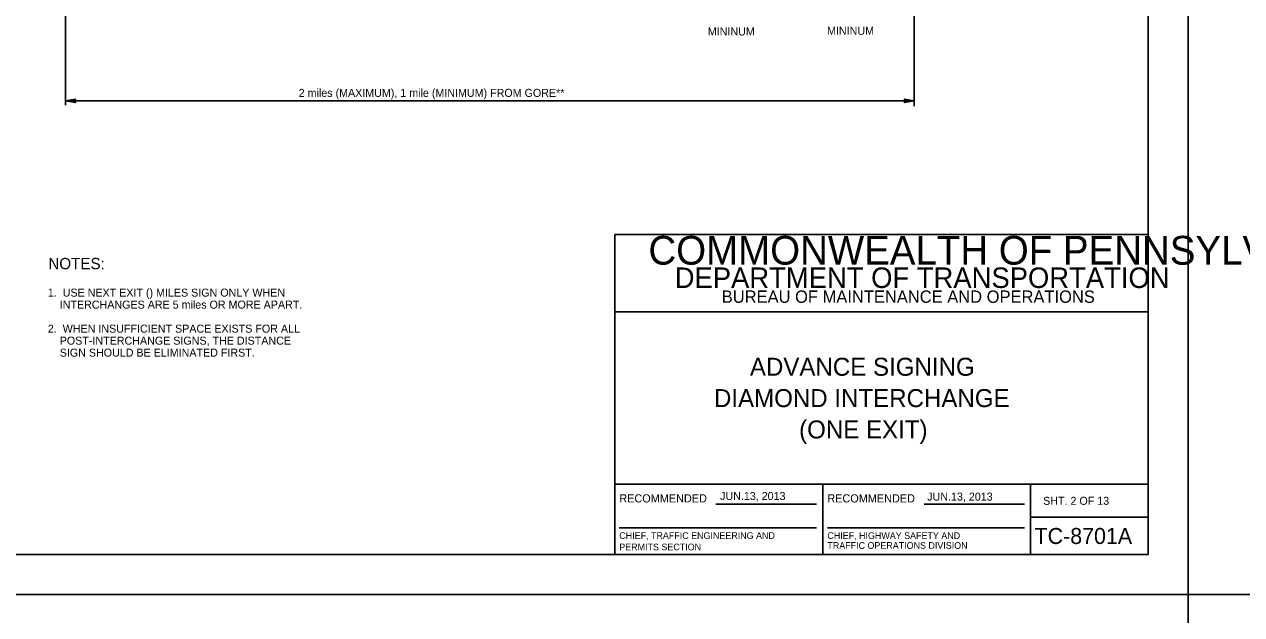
# Model space of a CAD drawing. Extents: x 644898 to 648326, y 298294 to 300670.
# Drawn here: x 646144 to 646600.3, y 300069 to 300290.3 of the extents above; entities that cross this region are included whole.
import ezdxf

# ---------------------------------------------------------------- set-up
doc = ezdxf.new("R2010")
doc.units = 0
for name, color, linetype in [('1', 7, 'Continuous'), ('2', 7, 'Continuous'), ('XCS-GRID-MIN', 7, 'Continuous')]:
    doc.layers.add(name, color=color, linetype=linetype)

msp = doc.modelspace()

# ---------------------------------------------------------------- linework, layer by layer
at = {"layer": '1'}
for p, q in [((646565.32, 300091.49), (646565.32, 300655.49)), ((646365.32, 300091.49), (646365.32, 300211.49)), ((646365.32, 300211.49), (646565.32, 300211.49)), ((646565.32, 300182.49), (646365.32, 300182.49)), ((646365.32, 300117.87), (646565.32, 300117.87)), ((646443.32, 300117.87), (646443.32, 300091.49)), ((646521.2, 300091.49), (646521.2, 300117.87)), ((646403.26, 300110.44), (646440.88, 300110.44)), ((646481.26, 300110.44), (646518.88, 300110.44)), ((646521.2, 300105.49), (646565.32, 300105.49)), ((646367.01, 300101.54), (646440.88, 300101.54)), ((646445.01, 300101.54), (646518.88, 300101.54)), ((646565.32, 300091.49), (645779.32, 300091.49)), ((645779.32, 300091.49), (646365.32, 300091.49))]:
    msp.add_line(p, q, dxfattribs=at)
at = {"layer": '2'}
for p, q in [((646477.57, 300377.74), (646477.57, 300259.62)), ((646159.45, 300363.62), (646159.45, 300259.99)), ((646477.57, 300261.62), (646159.45, 300261.62))]:
    msp.add_line(p, q, dxfattribs=at)
for points in [[(646162.95, 300261.12), (646162.82, 300261.37), (646159.45, 300261.62), (646162.95, 300261.12), (646163.2, 300260.99), (646159.45, 300261.62), (646162.82, 300261.74), (646162.95, 300261.99), (646159.45, 300261.62), (646163.2, 300262.24), (646162.95, 300261.99)], [(646474.07, 300262.12), (646474.2, 300261.87), (646477.57, 300261.62), (646474.07, 300262.12), (646473.82, 300262.24), (646477.57, 300261.62), (646474.2, 300261.49), (646474.07, 300261.24), (646477.57, 300261.62), (646473.82, 300260.99), (646474.07, 300261.24)]]:
    msp.add_lwpolyline(points, dxfattribs=at)
at = {"layer": 'XCS-GRID-MIN'}
for points in [[(645739.32, 300670.49), (646580.32, 300670.49), (646580.32, 300076.49), (645739.32, 300076.49)], [(646580.32, 300670.49), (647421.32, 300670.49), (647421.32, 300076.49), (646580.32, 300076.49)], [(645739.32, 300076.49), (646580.32, 300076.49), (646580.32, 299482.49), (645739.32, 299482.49)], [(646580.32, 300076.49), (647421.32, 300076.49), (647421.32, 299482.49), (646580.32, 299482.49)]]:
    msp.add_lwpolyline(points, close=True, dxfattribs=at)

# ---------------------------------------------------------------- texts
at = {"layer": '1'}
for s, height, p in [('COMMONWEALTH OF PENNSYLVANIA', 10.7828, (646377.92, 300200.22)), ('DEPARTMENT OF TRANSPORTATION', 7.6837, (646387.78, 300191.48)), ('BUREAU OF MAINTENANCE AND OPERATIONS', 4.6253, (646405.42, 300185.91)), ('ADVANCE SIGNING', 6.75, (646415.97, 300158.56)), ('DIAMOND INTERCHANGE', 6.75, (646402.5, 300146.81)), ('(ONE EXIT)', 6.75, (646434.42, 300135.06)), ('RECOMMENDED', 3.048, (646367.01, 300111.07)), ('JUN.13, 2013', 3, (646404.79, 300111.97)), ('RECOMMENDED', 3.048, (646445.01, 300111.07)), ('JUN.13, 2013', 3, (646482.45, 300111.76)), ('SHT. 2 OF 13', 3, (646525.91, 300110.18)), ('TC-8701A', 6, (646522.69, 300095.49)), ('CHIEF, TRAFFIC ENGINEERING AND', 2.5, (646367.01, 300097.38)), ('TRAFFIC OPERATIONS DIVISION', 2.5, (646445.01, 300093.68)), ('CHIEF, HIGHWAY SAFETY AND', 2.5, (646445.01, 300097.38)), ('PERMITS SECTION', 2.5, (646367.01, 300093.13))]:
    msp.add_text(s, height=height, dxfattribs=at).set_placement(p)
at = {"layer": '2'}
for s, height, p in [(' MININUM', 3, (646399.08, 300286.15)), (' MININUM', 3, (646443.78, 300286.41)), ('2 miles (MAXIMUM), 1 mile (MINIMUM) FROM GORE**', 3, (646246.81, 300263.12)), ('NOTES:', 4.25, (646152.98, 300198.5)), ('1.  USE NEXT EXIT () MILES SIGN ONLY WHEN', 3, (646152.77, 300188.23)), ('    INTERCHANGES ARE 5 miles OR MORE APART.', 3, (646152.77, 300183.73)), ('2.  WHEN INSUFFICIENT SPACE EXISTS FOR ALL', 3, (646152.77, 300174.73)), ('    POST-INTERCHANGE SIGNS, THE DISTANCE', 3, (646152.77, 300170.23)), ('    SIGN SHOULD BE ELIMINATED FIRST.', 3, (646152.77, 300165.73))]:
    msp.add_text(s, height=height, dxfattribs=at).set_placement(p)

doc.saveas('drawing.dxf')
